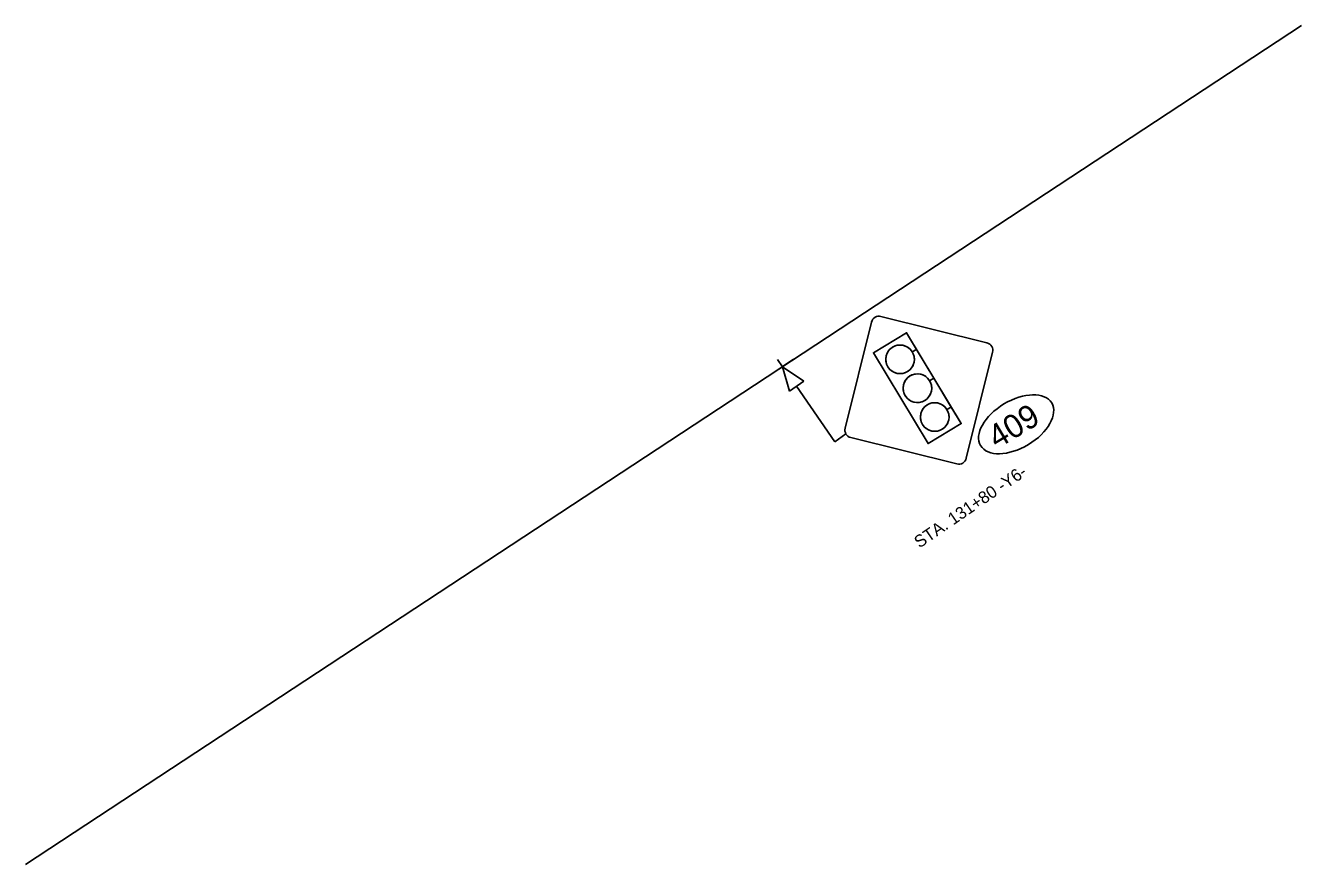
# Model space of a CAD drawing. Extents: x 1487362 to 2061618, y 497428 to 671257.
# Drawn here: x 1487811.6 to 1488145.8, y 497904.4 to 498124.2 of the extents above; entities that cross this region are included whole.
import ezdxf

# ---------------------------------------------------------------- set-up
doc = ezdxf.new("R2010")
doc.units = 0
for name, color, linetype in [('Prop Sign E Signal Light Ahead CELL', 7, 'Continuous'), ('Prop Support One', 7, 'Continuous'), ('Scratch_Level_1', 7, 'Continuous'), ('Text', 7, 'Continuous')]:
    doc.layers.add(name, color=color, linetype=linetype)

msp = doc.modelspace()

# ---------------------------------------------------------------- linework, layer by layer
at = {"layer": 'Prop Sign E Signal Light Ahead CELL'}
for p, q in [((1488033.19, 498046.48), (1488026.28, 498018.71)), ((1488063.43, 498041.05), (1488035.66, 498047.97)), ((1488058.01, 498010.82), (1488064.92, 498038.58)), ((1488052.96, 498023.55), (1488052.96, 498023.55)), ((1488052.96, 498023.55), (1488052.96, 498023.55)), ((1488027.77, 498016.24), (1488055.53, 498009.33))]:
    msp.add_line(p, q, dxfattribs=at)
msp.add_lwpolyline([(1488048.02, 498014.66), (1488056.71, 498019.89), (1488042.4, 498043.69), (1488033.71, 498038.46)], close=True, dxfattribs=at)
for points in [[(1488043.88, 498038.66), (1488045.01, 498039.34), (1488042.4, 498043.69), (1488033.71, 498038.46), (1488048.02, 498014.66), (1488056.71, 498019.89), (1488054.1, 498024.23), (1488052.96, 498023.55)], [(1488043.88, 498038.66), (1488045.01, 498039.34), (1488042.4, 498043.69), (1488033.71, 498038.46), (1488048.02, 498014.66), (1488056.71, 498019.89), (1488054.1, 498024.23), (1488052.96, 498023.55)], [(1488048.42, 498031.11), (1488049.55, 498031.79), (1488045.01, 498039.34), (1488043.88, 498038.66)], [(1488048.42, 498031.11), (1488049.55, 498031.79), (1488045.01, 498039.34), (1488043.88, 498038.66)], [(1488052.96, 498023.55), (1488054.1, 498024.23), (1488049.55, 498031.79), (1488048.42, 498031.11)], [(1488052.96, 498023.55), (1488054.1, 498024.23), (1488049.55, 498031.79), (1488048.42, 498031.11)]]:
    msp.add_lwpolyline(points, dxfattribs=at)
for centre in [(1488040.67, 498036.73), (1488040.67, 498036.73), (1488045.21, 498029.17), (1488045.21, 498029.17), (1488049.75, 498021.62), (1488049.75, 498021.62)]:
    msp.add_circle(centre, 3.75, dxfattribs=at)
for centre, radius, start, end in [((1488035.17, 498045.99), 2.04, 76.022, 166.022), ((1488040.67, 498036.73), 3.75, 31.0273, 31.022), ((1488040.67, 498036.73), 3.75, 31.0273, 31.022), ((1488062.94, 498039.07), 2.04, 346.022, 76.022), ((1488045.21, 498029.17), 3.75, 31.0273, 31.022), ((1488045.21, 498029.17), 3.75, 31.0273, 31.022), ((1488049.75, 498021.62), 3.75, 31.0273, 31.022), ((1488049.75, 498021.62), 3.75, 31.0273, 31.022), ((1488028.26, 498018.22), 2.04, 166.022, 256.022), ((1488056.03, 498011.31), 2.04, 256.022, 346.022)]:
    msp.add_arc(centre, radius, start, end, dxfattribs=at)
msp.add_ellipse((1488071.08, 498019.71), major_axis=(-9.31, -5.59), ratio=0.571429, dxfattribs=at)
at = {"layer": 'Prop Support One'}
for p, q in [((1488012.74, 498036.74), (1488007.13, 498032.89)), ((1488009.91, 498034.8), (1488008.6, 498036.71)), ((1488011.69, 498028.39), (1488009.91, 498034.8)), ((1488009.91, 498034.8), (1488015.46, 498030.97)), ((1488015.46, 498030.97), (1488011.69, 498028.39)), ((1488023.55, 498015.14), (1488013.57, 498029.68)), ((1488023.55, 498015.14), (1488026.51, 498017.17))]:
    msp.add_line(p, q, dxfattribs=at)
at = {"layer": 'Scratch_Level_1'}
msp.add_line((1488145.82, 498124.18), (1487811.61, 497904.39), dxfattribs=at)

# ---------------------------------------------------------------- texts
at = {"layer": 'Prop Sign E Signal Light Ahead CELL'}
msp.add_text('409', height=6.132, rotation=30.9879, dxfattribs=at).set_placement((1488066.08, 498013.13))
at = {"layer": 'Text'}
msp.add_text('STA. 131+80 -Y6-', height=3.2, rotation=34.361, dxfattribs=at).set_placement((1488045.76, 497987.15))

doc.saveas('drawing.dxf')
